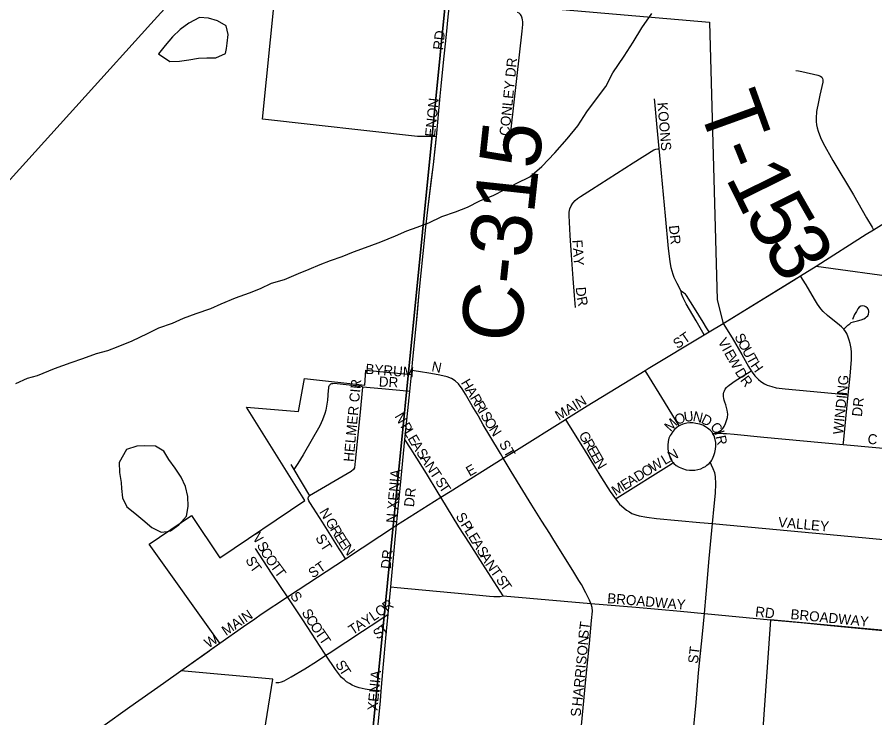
# Model space of a CAD drawing. Extents: x 0 to 680, y 0 to 440.
# Drawn here: x 231.14 to 243.78, y 264.87 to 275.19 of the extents above; entities that cross this region are included whole.
import ezdxf

# ---------------------------------------------------------------- set-up
doc = ezdxf.new("R2010")
doc.units = 0
for name, color, linetype in [('GM_X_City_Street', 7, 'Continuous'), ('GM_X_City_Street_Text', 7, 'Continuous'), ('GM_X_Corporation', 7, 'Continuous'), ('GM_X_County_Road', 7, 'Continuous'), ('GM_X_County_Road_Text', 7, 'Continuous'), ('GM_X_Minor_Lake', 7, 'Continuous'), ('GM_X_Minor_River', 7, 'Continuous'), ('GM_X_Rail_Line', 7, 'Continuous'), ('GM_X_Section', 7, 'Continuous'), ('GM_X_Township_Road', 7, 'Continuous'), ('GM_X_Township_Road_Text', 7, 'Continuous')]:
    doc.layers.add(name, color=color, linetype=linetype)

msp = doc.modelspace()

# ---------------------------------------------------------------- linework, layer by layer
at = {"layer": 'GM_X_City_Street'}
for points in [[(238.405, 273.403), (238.416, 273.547), (238.577, 274.988), (238.587, 275.085), (238.588, 275.125), (238.584, 275.154), (238.58, 275.178), (238.57, 275.207), (238.565, 275.218), (238.556, 275.231), (238.545, 275.241), (238.533, 275.25), (238.512, 275.262)], [(237.312, 273.396), (237.315, 273.428), (237.37, 274.027), (237.384, 274.176), (237.41, 274.424), (237.43, 274.616), (237.463, 274.938)], [(240.597, 273.259), (240.568, 273.566), (240.533, 273.943), (240.529, 273.99)], [(239.364, 270.918), (239.349, 271.093), (239.33, 271.341), (239.306, 271.686), (239.286, 271.977), (239.271, 272.272), (239.273, 272.32), (239.284, 272.368), (239.302, 272.413), (239.327, 272.454), (239.359, 272.491), (239.397, 272.522), (239.437, 272.549), (239.599, 272.656), (240.217, 273.044), (240.52, 273.238), (240.547, 273.247), (240.583, 273.255), (240.597, 273.259)], [(240.923, 271.156), (240.862, 271.269), (240.82, 271.357), (240.803, 271.403), (240.777, 271.498), (240.759, 271.594), (240.736, 271.786), (240.691, 272.267), (240.632, 272.892), (240.597, 273.259)], [(243.321, 270.594), (243.286, 270.63), (243.224, 270.681), (243.158, 270.733), (243.078, 270.798), (243.016, 270.858), (242.979, 270.897), (242.931, 270.967), (242.888, 271.038), (242.767, 271.248), (242.711, 271.334), (242.681, 271.381)], [(241.334, 270.555), (241.296, 270.617), (241.245, 270.698), (241.12, 270.907), (241.003, 271.09), (240.984, 271.113), (240.958, 271.134), (240.923, 271.156)], [(241.263, 270.512), (241.222, 270.582), (241.142, 270.721), (241.043, 270.884), (240.995, 270.968), (240.951, 271.058), (240.935, 271.093), (240.929, 271.118), (240.923, 271.156)], [(243.321, 270.594), (243.381, 270.654), (243.407, 270.675), (243.43, 270.693), (243.462, 270.704), (243.521, 270.718), (243.577, 270.735), (243.616, 270.75), (243.64, 270.762), (243.656, 270.777), (243.671, 270.795), (243.682, 270.819), (243.688, 270.846), (243.69, 270.861), (243.684, 270.884), (243.669, 270.906), (243.645, 270.927), (243.625, 270.935), (243.601, 270.939), (243.57, 270.934), (243.548, 270.92), (243.527, 270.894), (243.504, 270.857), (243.479, 270.811), (243.445, 270.738)], [(241.543, 270.68), (241.673, 270.47), (241.818, 270.221), (241.914, 270.047), (241.955, 269.984)], [(240.393, 269.989), (240.436, 270.015), (241.263, 270.512)], [(241.263, 270.512), (241.334, 270.555)], [(243.385, 269.63), (243.413, 269.903), (243.434, 270.15), (243.434, 270.205), (243.431, 270.256), (243.428, 270.312), (243.411, 270.385), (243.4, 270.432), (243.385, 270.479), (243.362, 270.531), (243.344, 270.563), (243.321, 270.594)], [(238.299, 268.695), (238.258, 268.764), (238.104, 269.025), (238.005, 269.189), (237.935, 269.313), (237.916, 269.351), (237.842, 269.468), (237.746, 269.637), (237.695, 269.719), (237.639, 269.79), (237.594, 269.835), (237.537, 269.871), (237.476, 269.894), (237.366, 269.919), (237.233, 269.942), (237.051, 269.972), (236.954, 269.988)], [(239.216, 269.268), (239.223, 269.272), (239.539, 269.469), (240.393, 269.989)], [(240.893, 269.172), (240.839, 269.26), (240.637, 269.592), (240.457, 269.884), (240.393, 269.989)], [(241.391, 269.057), (241.451, 269.076), (241.488, 269.093), (241.512, 269.111), (241.536, 269.133), (241.556, 269.165), (241.577, 269.206), (241.593, 269.252), (241.604, 269.293), (241.608, 269.343), (241.605, 269.373), (241.602, 269.405), (241.579, 269.481), (241.567, 269.523), (241.558, 269.55), (241.55, 269.577), (241.546, 269.603), (241.545, 269.626), (241.547, 269.643), (241.553, 269.666), (241.561, 269.688), (241.571, 269.711), (241.589, 269.736), (241.604, 269.752), (241.628, 269.774), (241.717, 269.834), (241.9, 269.949), (241.923, 269.963), (241.955, 269.984)], [(241.955, 269.984), (241.967, 269.965), (242.008, 269.908), (242.061, 269.855), (242.099, 269.825), (242.15, 269.793), (242.188, 269.774), (242.258, 269.751), (242.323, 269.734), (242.457, 269.717), (243.35, 269.634), (243.385, 269.63)], [(236.922, 269.678), (236.947, 269.924), (236.948, 269.929), (236.951, 269.957)], [(236.225, 269.742), (236.211, 269.751), (236.202, 269.755), (236.193, 269.756), (236.158, 269.759), (236.135, 269.762), (236.031, 269.773), (235.811, 269.794), (235.79, 269.793), (235.769, 269.79), (235.755, 269.784), (235.747, 269.778), (235.739, 269.769), (235.731, 269.755), (235.727, 269.741), (235.725, 269.724), (235.723, 269.698), (235.709, 269.551), (235.686, 269.405), (235.673, 269.356), (235.639, 269.262), (235.596, 269.172), (235.35, 268.746), (235.272, 268.62), (235.216, 268.528)], [(236.225, 269.742), (236.187, 269.326), (236.171, 269.183), (236.156, 269.039), (236.118, 268.653), (236.11, 268.554)], [(236.922, 269.678), (236.88, 269.682), (236.511, 269.716), (236.225, 269.742)], [(236.852, 268.97), (236.894, 269.4), (236.922, 269.678)], [(243.312, 268.898), (243.314, 268.92), (243.385, 269.63)], [(238.299, 268.695), (238.494, 268.816), (239.216, 269.268)], [(239.216, 269.268), (239.264, 269.191), (239.495, 268.823), (239.646, 268.574), (239.747, 268.409), (239.878, 268.205), (239.954, 268.097)], [(240.893, 269.172), (240.862, 269.151), (240.826, 269.119), (240.8, 269.089), (240.774, 269.052), (240.761, 269.028), (240.743, 268.992), (240.731, 268.941), (240.727, 268.89), (240.724, 268.844), (240.731, 268.791), (240.745, 268.746), (240.761, 268.703), (240.782, 268.659), (240.804, 268.631)], [(241.391, 269.057), (241.377, 269.079), (241.349, 269.11), (241.312, 269.14), (241.282, 269.16), (241.24, 269.181), (241.197, 269.196), (241.14, 269.209), (241.093, 269.215), (241.052, 269.217), (241.004, 269.214), (240.946, 269.199), (240.902, 269.178), (240.893, 269.172)], [(236.73, 267.709), (236.787, 268.3), (236.852, 268.97)], [(237.383, 268.123), (237.344, 268.186), (237.171, 268.468), (236.969, 268.789), (236.943, 268.828), (236.852, 268.97)], [(241.352, 268.636), (241.359, 268.643), (241.375, 268.669), (241.386, 268.685), (241.405, 268.734), (241.42, 268.782), (241.427, 268.829), (241.432, 268.875), (241.432, 268.926), (241.423, 268.973), (241.408, 269.025), (241.391, 269.057)], [(241.391, 269.057), (241.474, 269.065), (241.542, 269.062), (241.593, 269.059), (241.704, 269.049), (242.141, 269.008), (243.312, 268.898)], [(243.312, 268.898), (244.809, 268.758), (244.904, 268.748)], [(235.17, 268.602), (235.216, 268.528)], [(237.383, 268.123), (237.516, 268.207), (238.299, 268.695)], [(239.592, 266.558), (239.574, 266.605), (239.52, 266.714), (239.452, 266.833), (239.416, 266.894), (239.339, 267.018), (239.032, 267.514), (238.987, 267.586), (238.869, 267.77), (238.722, 268.005), (238.418, 268.502), (238.299, 268.695)], [(239.954, 268.097), (239.978, 268.113), (240.778, 268.615), (240.804, 268.631)], [(240.804, 268.631), (240.813, 268.619), (240.851, 268.588), (240.891, 268.565), (240.944, 268.543), (240.995, 268.526), (241.047, 268.519), (241.086, 268.519), (241.123, 268.52), (241.167, 268.528), (241.212, 268.541), (241.248, 268.558), (241.279, 268.574), (241.302, 268.591), (241.335, 268.618), (241.352, 268.636)], [(241.386, 267.735), (241.411, 267.988), (241.427, 268.181), (241.433, 268.318), (241.427, 268.425), (241.417, 268.479), (241.396, 268.541), (241.371, 268.595), (241.352, 268.636)], [(235.216, 268.528), (235.446, 268.143)], [(236.11, 268.554), (236.092, 268.528), (236.061, 268.499), (235.446, 268.143)], [(235.976, 267.214), (235.921, 267.301), (235.883, 267.362), (235.635, 267.754), (235.505, 267.959), (235.451, 268.045), (235.438, 268.068), (235.431, 268.084), (235.428, 268.095), (235.427, 268.105), (235.428, 268.112), (235.429, 268.12), (235.432, 268.127), (235.438, 268.134), (235.446, 268.143)], [(236.73, 267.709), (237.383, 268.123)], [(238.297, 266.67), (238.032, 267.081), (237.801, 267.446), (237.646, 267.687), (237.383, 268.123)], [(239.954, 268.097), (239.958, 268.091), (240.016, 268.019), (240.076, 267.963), (240.119, 267.932), (240.16, 267.904), (240.197, 267.881), (240.254, 267.861), (240.305, 267.848), (240.417, 267.825), (240.557, 267.808), (241.198, 267.751), (241.386, 267.735)], [(235.976, 267.214), (236.73, 267.709)], [(236.642, 266.801), (236.662, 267.018), (236.73, 267.709)], [(241.265, 266.408), (241.292, 266.691), (241.336, 267.217), (241.386, 267.735)], [(241.386, 267.735), (241.434, 267.731), (243.588, 267.529), (244.687, 267.426), (244.778, 267.418)], [(235.119, 266.653), (234.897, 266.99), (234.758, 267.197), (234.652, 267.367)], [(235.119, 266.653), (235.28, 266.759), (235.976, 267.214)], [(236.604, 266.398), (236.642, 266.801)], [(236.642, 266.801), (236.735, 266.793), (237.949, 266.677), (238.1, 266.663), (238.162, 266.658), (238.215, 266.658), (238.254, 266.661), (238.297, 266.67)], [(234.638, 266.33), (234.735, 266.397), (235.119, 266.653)], [(235.686, 265.793), (235.666, 265.824), (235.347, 266.313), (235.119, 266.653)], [(238.297, 266.67), (239.592, 266.558)], [(239.421, 264.403), (239.439, 264.599), (239.517, 265.436), (239.571, 265.968), (239.599, 266.306), (239.614, 266.445), (239.61, 266.496), (239.597, 266.546), (239.592, 266.558)], [(239.592, 266.558), (240.256, 266.501), (240.912, 266.441), (241.265, 266.408)], [(233.946, 265.844), (234.012, 265.891), (234.125, 265.97), (234.475, 266.216), (234.638, 266.33)], [(235.686, 265.793), (235.734, 265.825), (236.227, 266.146), (236.469, 266.307), (236.604, 266.398)], [(236.501, 265.265), (236.53, 265.609), (236.576, 266.097), (236.604, 266.398)], [(241.065, 264.259), (241.1, 264.645), (241.142, 265.096), (241.18, 265.532), (241.235, 266.104), (241.265, 266.408)], [(241.265, 266.408), (242.241, 266.315)], [(242.241, 266.315), (242.687, 266.274), (243.074, 266.236), (243.685, 266.178), (244.662, 266.089)], [(234.948, 265.39), (234.992, 265.392), (235.034, 265.401), (235.074, 265.416), (235.177, 265.476), (235.375, 265.594), (235.548, 265.701), (235.686, 265.793)], [(236.501, 265.265), (236.468, 265.269), (236.361, 265.28), (236.264, 265.295), (236.176, 265.313), (236.12, 265.334), (236.076, 265.353), (236.033, 265.376), (235.992, 265.403), (235.954, 265.434), (235.919, 265.468), (235.887, 265.504), (235.829, 265.582), (235.686, 265.793)], [(236.446, 264.674), (236.49, 265.123), (236.501, 265.265)]]:
    msp.add_lwpolyline(points, dxfattribs=at)
at = {"layer": 'GM_X_Corporation'}
for points in [[(234.701, 264.154), (234.903, 265.441), (233.551, 265.562), (234.125, 265.97), (233.082, 267.429), (233.706, 267.851), (234.125, 267.23), (235.376, 268.071), (234.518, 269.446), (235.281, 269.384), (235.37, 269.871), (236.262, 269.77), (236.277, 269.994), (236.948, 269.929), (236.954, 269.988), (236.969, 270.156), (237.017, 270.64), (237.064, 271.13), (237.122, 271.712), (237.161, 272.1), (237.196, 272.4), (237.271, 273.024), (237.315, 273.428), (237.232, 273.432), (237.036, 273.434), (234.753, 273.689), (234.929, 275.445)], [(237.514, 275.451), (241.339, 275.12), (241.452, 271.027), (241.543, 270.68), (242.681, 271.381), (242.911, 271.523), (244.202, 271.348), (244.031, 269.569), (246.397, 269.338), (246.584, 271.153), (247.693, 271.048), (247.217, 265.846), (246.56, 265.91), (244.662, 266.089), (242.241, 266.315), (241.873, 261.084), (241.575, 261.102), (240.608, 250.172), (240.901, 250.147), (240.558, 246.017)]]:
    msp.add_lwpolyline(points, dxfattribs=at)
at = {"layer": 'GM_X_County_Road'}
for points in [[(243.758, 272.062), (244.425, 272.476), (244.838, 272.732), (245.296, 273.009), (245.757, 273.28), (246.175, 273.528), (246.947, 273.979), (247.213, 274.128), (248.202, 274.684), (249.606, 275.46), (249.987, 275.673), (251.774, 276.667), (252.753, 277.216), (253.682, 277.731), (253.723, 277.754)], [(237.463, 274.938), (237.49, 275.199), (237.507, 275.374)], [(237.245, 272.805), (237.271, 273.024), (237.312, 273.396)], [(237.03, 270.782), (237.064, 271.13), (237.122, 271.712), (237.161, 272.1), (237.196, 272.4), (237.245, 272.805)], [(242.681, 271.381), (242.911, 271.523), (242.927, 271.534), (243.649, 271.995), (243.758, 272.062)], [(241.543, 270.68), (242.163, 271.063), (242.574, 271.315), (242.681, 271.381)], [(236.954, 269.988), (236.969, 270.156), (237.017, 270.64), (237.03, 270.782)], [(241.334, 270.555), (241.543, 270.68)], [(236.951, 269.957), (236.954, 269.988)], [(233.295, 265.382), (233.551, 265.562), (233.946, 265.844)], [(232.399, 264.75), (232.797, 265.032), (233.295, 265.382)]]:
    msp.add_lwpolyline(points, dxfattribs=at)
at = {"layer": 'GM_X_Minor_Lake'}
for points in [[(234.221, 274.731), (234.234, 274.807), (234.248, 274.938), (234.219, 275.063), (234.089, 275.136), (233.959, 275.179), (233.822, 275.187), (233.667, 275.105), (233.541, 275.012), (233.427, 274.9), (233.318, 274.777), (233.221, 274.653)], [(233.221, 274.653), (233.386, 274.538), (233.529, 274.542), (233.666, 274.564), (233.809, 274.586), (233.934, 274.591), (234.065, 274.595), (234.208, 274.659), (234.221, 274.731)], [(233.346, 267.618), (233.396, 267.626), (233.522, 267.714), (233.631, 267.843), (233.656, 267.986), (233.652, 268.134), (233.618, 268.277), (233.555, 268.415), (233.467, 268.547), (233.374, 268.679), (233.298, 268.798), (233.174, 268.871), (233.019, 268.879), (232.9, 268.875), (232.751, 268.823)], [(232.751, 268.823), (232.642, 268.634), (232.646, 268.486), (232.668, 268.337), (232.673, 268.248), (232.689, 268.111), (232.753, 267.979), (232.87, 267.888), (232.988, 267.786), (233.123, 267.677), (233.259, 267.604), (233.346, 267.618)]]:
    msp.add_lwpolyline(points, dxfattribs=at)
at = {"layer": 'GM_X_Minor_River'}
msp.add_lwpolyline([(231.116, 269.794), (231.289, 269.875), (231.438, 269.915), (231.689, 270.019), (231.934, 270.105), (232.107, 270.162), (232.305, 270.237), (232.472, 270.282), (232.627, 270.34), (232.83, 270.427), (233.057, 270.531), (233.225, 270.618), (233.428, 270.687), (233.589, 270.756), (233.775, 270.825), (233.99, 270.9), (234.145, 270.969), (234.354, 271.056), (234.563, 271.13), (234.725, 271.194), (234.886, 271.275), (235.077, 271.326), (235.281, 271.418), (235.442, 271.482), (235.603, 271.551), (235.753, 271.609), (235.926, 271.666), (236.093, 271.735), (236.326, 271.821), (236.499, 271.885), (236.714, 271.971), (236.882, 272.046), (237.031, 272.098), (237.204, 272.161), (237.396, 272.254), (237.599, 272.323), (237.772, 272.392), (237.958, 272.485), (238.161, 272.571), (238.316, 272.647), (238.502, 272.745), (238.693, 272.838), (238.868, 272.99), (239.061, 273.196), (239.242, 273.402), (239.398, 273.59), (239.532, 273.796), (239.677, 273.991), (239.81, 274.173), (239.914, 274.374), (240.083, 274.616), (240.216, 274.822), (240.344, 275.034), (240.489, 275.246)], dxfattribs=at)
at = {"layer": 'GM_X_Rail_Line'}
msp.add_lwpolyline([(215.274, 255.394), (220.659, 261.341), (221.118, 261.846), (223.655, 264.643), (227.232, 268.601), (228.124, 269.614), (228.567, 270.075), (229.213, 270.794), (230.659, 272.394), (232.139, 274.024), (233.106, 275.096), (234.056, 276.142), (234.345, 276.443), (234.953, 277.039), (235.362, 277.445), (236.033, 277.963), (236.439, 278.272), (237.087, 278.73), (238.028, 279.373), (238.48, 279.693), (238.914, 280.034), (239.194, 280.264), (239.864, 280.845), (240.308, 281.194)], dxfattribs=at)
at = {"layer": 'GM_X_Section'}
for points in [[(221.851, 279.108), (237.63, 277.245), (236.072, 261.647), (220.69, 263.141), (220.359, 263.176)], [(237.63, 277.245), (253.475, 275.778), (251.886, 260.08), (236.416, 261.612), (236.072, 261.647)]]:
    msp.add_lwpolyline(points, close=True, dxfattribs=at)
at = {"layer": 'GM_X_Township_Road'}
msp.add_lwpolyline([(242.611, 274.407), (242.65, 274.401), (242.7, 274.392), (242.939, 274.338), (242.977, 274.323), (242.996, 274.306), (243.006, 274.29), (243.011, 274.269), (243.008, 274.233), (242.965, 274.042), (242.946, 273.947), (242.919, 273.803), (242.91, 273.705), (242.91, 273.656), (242.915, 273.608), (242.926, 273.56), (242.94, 273.513), (242.974, 273.422), (243.016, 273.335), (243.16, 273.079), (243.461, 272.576), (243.653, 272.236), (243.737, 272.097), (243.758, 272.062)], dxfattribs=at)

# ---------------------------------------------------------------- texts
at = {"layer": 'GM_X_City_Street_Text'}
for s, height, rotation, p in [('RD', 0.1482, 83.6631, (237.412, 274.703)), ('CONLEY DR', 0.1482, 84.218, (238.39, 273.437)), ('ENON', 0.1482, 84.1471, (237.294, 273.424)), ('KOONS', 0.1482, 274.7655, (240.572, 273.932)), ('DR', 0.1482, 276.006, (240.741, 272.12)), ('FAY', 0.1482, 274.0909, (239.318, 271.909)), ('D', 0.148, 273.6309, (239.37, 271.214)), ('R', 0.148, 282.0308, (239.381, 271.061)), ('ST', 0.1482, 34.6965, (240.867, 270.3)), ('V', 0.148, 299.1756, (241.457, 270.416)), ('S', 0.148, 298.6977, (241.703, 270.486)), ('I', 0.148, 299.1756, (241.52, 270.302)), ('O', 0.148, 298.6767, (241.753, 270.395)), ('E', 0.148, 299.1856, (241.552, 270.245)), ('U', 0.148, 298.6997, (241.816, 270.28)), ('T', 0.148, 298.6672, (241.879, 270.166)), ('N', 0.148, 348.6943, (237.236, 269.979)), ('W', 0.148, 299.3071, (241.603, 270.154)), ('H', 0.148, 304.7786, (241.938, 270.06)), ('BYRUM', 0.1482, 355.5144, (236.265, 269.94)), ('D', 0.148, 301.8724, (241.709, 269.966)), ('DR', 0.1482, 356.989, (236.464, 269.753)), ('H', 0.148, 300.7913, (237.672, 269.809)), ('R', 0.148, 307.0932, (241.786, 269.843)), ('WINDING', 0.1482, 84.4709, (243.308, 269.04)), ('HELMER CIR', 0.1482, 84.62, (236.094, 268.637)), ('A', 0.148, 300.812, (237.739, 269.697)), ('R', 0.148, 300.793, (237.806, 269.585)), ('MAIN', 0.1482, 31.3716, (239.121, 269.245)), ('R', 0.148, 300.7988, (237.866, 269.484)), ('DR', 0.1482, 83.9832, (243.585, 269.302)), ('N', 0.148, 300.542, (236.694, 269.313)), ('I', 0.148, 300.7913, (237.926, 269.383)), ('S', 0.148, 300.8034, (237.959, 269.327)), ('O', 0.148, 21.6228, (240.859, 269.183)), ('U', 0.148, 7.3094, (240.971, 269.229)), ('N', 0.148, 347.4854, (241.086, 269.246)), ('P', 0.148, 300.5514, (236.78, 269.167)), ('O', 0.148, 300.7913, (238.013, 269.237)), ('M', 0.148, 47.2093, (240.767, 269.078)), ('D', 0.148, 333.4154, (241.205, 269.221)), ('L', 0.148, 300.5599, (236.833, 269.077)), ('N', 0.148, 303.004, (238.083, 269.12)), ('C', 0.148, 311.4944, (241.341, 269.148)), ('I', 0.148, 290.1288, (241.411, 269.073)), ('E', 0.148, 300.5514, (236.886, 268.987)), ('G', 0.148, 299.856, (239.407, 269.039)), ('R', 0.148, 299.874, (239.472, 268.926)), ('R', 0.148, 281.1694, (241.432, 269.018)), ('C', 0.148, 354.0139, (243.664, 268.91)), ('A', 0.148, 301.3163, (236.94, 268.896)), ('ST', 0.1482, 299.7432, (238.233, 268.909)), ('E', 0.148, 299.8533, (239.531, 268.824)), ('S', 0.148, 303.0876, (237.011, 268.78)), ('A', 0.148, 303.4241, (237.068, 268.692)), ('E', 0.148, 299.8657, (239.583, 268.733)), ('L', 0.148, 30.9192, (240.683, 268.593)), ('N', 0.148, 27.4252, (240.771, 268.646)), ('N', 0.148, 303.4234, (237.14, 268.583)), ('E', 0.148, 29.7432, (237.804, 268.423)), ('N', 0.148, 301.5131, (239.637, 268.639)), ('O', 0.148, 32.1351, (240.397, 268.413)), ('W', 0.148, 32.1527, (240.507, 268.483)), ('N XENIA', 0.1482, 84.9859, (236.721, 267.736)), ('T', 0.148, 303.4173, (237.212, 268.474)), ('D', 0.148, 32.156, (240.286, 268.344)), ('S', 0.148, 303.4402, (237.291, 268.354)), ('T', 0.148, 303.4248, (237.348, 268.267)), ('M', 0.148, 32.1541, (239.955, 268.136)), ('E', 0.148, 32.1328, (240.088, 268.219)), ('A', 0.148, 32.1546, (240.176, 268.275)), ('DR', 0.1482, 83.994, (236.984, 267.971)), ('N', 0.148, 301.4285, (235.585, 267.905)), ('S', 0.148, 301.5681, (237.594, 267.84)), ('VALLEY', 0.1482, 354.8053, (242.347, 267.683)), ('G', 0.148, 301.4099, (235.673, 267.76)), ('R', 0.148, 301.4423, (235.741, 267.649)), ('P', 0.148, 301.5681, (237.669, 267.717)), ('N', 0.148, 299.1321, (234.581, 267.565)), ('E', 0.148, 301.416, (235.802, 267.549)), ('L', 0.148, 301.5675, (237.723, 267.629)), ('E', 0.148, 301.5675, (237.778, 267.54)), ('S', 0.148, 299.1382, (234.664, 267.417)), ('ST', 0.1482, 302.7321, (235.526, 267.52)), ('E', 0.148, 302.9952, (235.859, 267.456)), ('A', 0.148, 301.5617, (237.833, 267.451)), ('C', 0.148, 300.1553, (234.716, 267.323)), ('N', 0.148, 307.8269, (235.924, 267.357)), ('DR', 0.1482, 83.9946, (236.642, 267.058)), ('S', 0.148, 301.587, (237.901, 267.34)), ('S', 0.148, 297.8298, (234.497, 267.201)), ('O', 0.148, 305.3742, (234.783, 267.209)), ('A', 0.148, 301.6098, (237.956, 267.251)), ('N', 0.148, 303.9567, (238.028, 267.134)), ('T', 0.148, 306.3855, (234.559, 267.088)), ('T', 0.148, 306.4585, (234.86, 267.1)), ('T', 0.148, 306.4757, (234.922, 267.016)), ('ST', 0.1482, 34.6908, (235.493, 266.922)), ('T', 0.148, 305.293, (238.103, 267.023)), ('S', 0.148, 305.3423, (238.186, 266.905)), ('T', 0.148, 305.3831, (238.246, 266.82)), ('S', 0.148, 305.5229, (235.153, 266.667)), ('BROADWAY', 0.1482, 355.1207, (239.829, 266.562)), ('R', 0.148, 35.847, (236.585, 266.426)), ('MAIN', 0.1482, 34.1159, (234.215, 266.074)), ('S', 0.148, 298.0741, (235.326, 266.428)), ('O', 0.148, 35.5677, (236.478, 266.35)), ('RD', 0.1482, 353.6638, (242.008, 266.366)), ('BROADWAY', 0.1482, 354.4269, (242.529, 266.327)), ('C', 0.148, 302.9999, (235.382, 266.324)), ('Y', 0.148, 33.2566, (236.277, 266.216)), ('L', 0.148, 34.0285, (236.388, 266.289)), ('O', 0.148, 304.2799, (235.448, 266.222)), ('T', 0.148, 304.3957, (235.521, 266.114)), ('T', 0.148, 33.2506, (236.081, 266.087)), ('A', 0.148, 33.2618, (236.168, 266.145)), ('S', 0.148, 33.781, (236.444, 266.019)), ('T', 0.148, 35.9948, (236.535, 266.08)), ('ST', 0.1482, 82.8783, (239.551, 266.028)), ('W', 0.148, 32.4763, (233.955, 265.892)), ('T', 0.148, 304.3798, (235.58, 266.028)), ('HARRISON', 0.1482, 84.3693, (239.46, 265.036)), ('ST', 0.1482, 82.8792, (241.168, 265.663)), ('S', 0.148, 302.8641, (235.819, 265.661)), ('T', 0.148, 302.379, (235.876, 265.574)), ('XENIA', 0.1482, 84.6814, (236.446, 264.971)), ('S', 0.148, 90, (239.446, 264.89))]:
    msp.add_text(s, height=height, rotation=rotation, dxfattribs=at).set_placement(p)
at = {"layer": 'GM_X_County_Road_Text'}
msp.add_text('C-315', height=0.8894, rotation=83.8748, dxfattribs=at).set_placement((238.548, 270.376))
at = {"layer": 'GM_X_Township_Road_Text'}
for s, rotation, p in [('T', 289.8195, (241.164, 273.895)), ('-', 292.0561, (241.403, 273.234)), ('1', 296.3115, (241.569, 272.829)), ('5', 299.8199, (241.84, 272.286)), ('3', 300.2764, (242.116, 271.804))]:
    msp.add_text(s, height=0.889, rotation=rotation, dxfattribs=at).set_placement(p)

doc.saveas('drawing.dxf')
